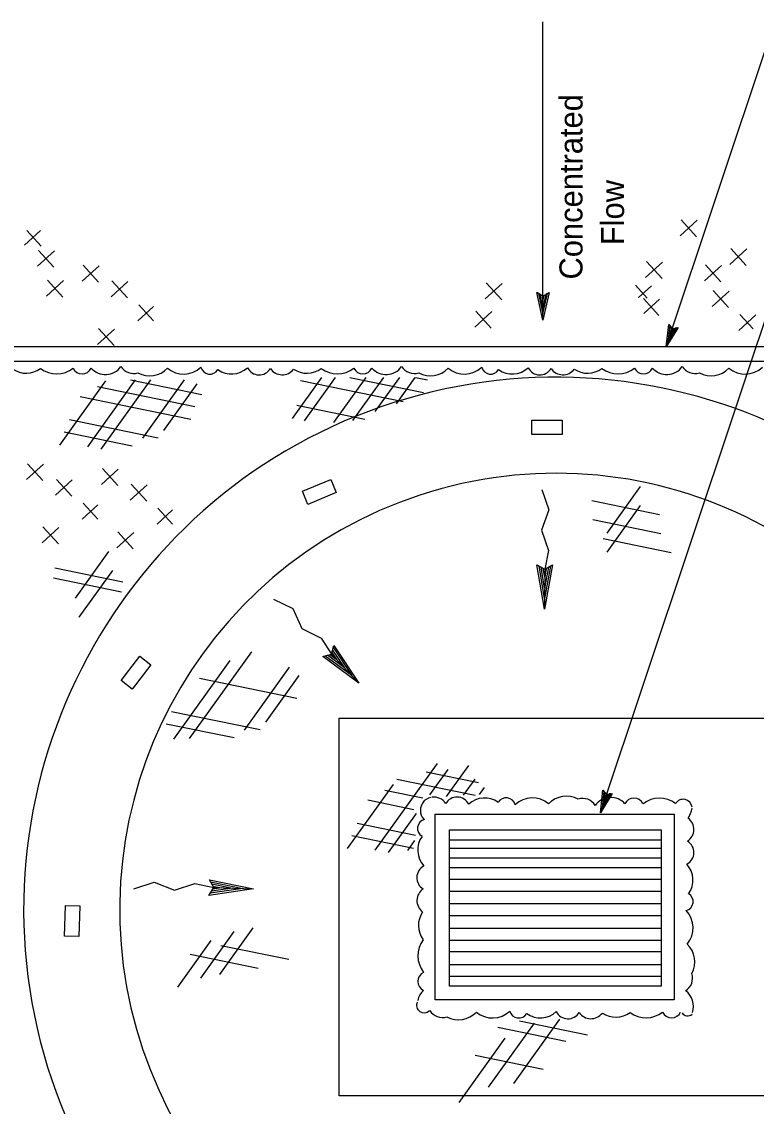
# Model space of a CAD drawing. Extents: x 6708945 to 6710368, y 1871409 to 1872338.
# Drawn here: x 6709044.1 to 6709235.1, y 1871623 to 1871904.9 of the extents above; entities that cross this region are included whole.
import ezdxf

# ---------------------------------------------------------------- set-up
doc = ezdxf.new("R2010")
doc.units = 0
for name, color, linetype in [('1 Control', 7, 'Continuous'), ('57 Undefined', 7, 'Continuous'), ('60 Nongeo Data', 7, 'Continuous'), ('62 As-Built Chng', 7, 'Continuous'), ('63 Undefined', 7, 'Continuous')]:
    doc.layers.add(name, color=color, linetype=linetype)

msp = doc.modelspace()

# ---------------------------------------------------------------- linework, layer by layer
at = {"layer": '1 Control'}
for p, q in [((6709178.02, 1871834.47), (6709178.02, 1871834.47)), ((6709181.22, 1871834.47), (6709181.22, 1871834.47)), ((6709179.61, 1871827.27), (6709179.61, 1871827.27))]:
    msp.add_line(p, q, dxfattribs=at)
msp.add_lwpolyline([(6709181.22, 1871834.47), (6709179.61, 1871827.27), (6709178.01, 1871834.47), (6709178.44, 1871834.21), (6709179.61, 1871828.93), (6709180.79, 1871834.21), (6709180.37, 1871833.96), (6709179.61, 1871830.58), (6709178.87, 1871833.95), (6709179.29, 1871833.7), (6709179.62, 1871832.24), (6709179.94, 1871833.7), (6709179.61, 1871833.51), (6709178.01, 1871834.47), (6709179.61, 1871833.51)], close=True, dxfattribs=at)
at = {"layer": '57 Undefined'}
for p, q in [((6709179.61, 1871827.27), (6709179.61, 1871904.86)), ((6709211.7, 1871820.34), (6709238.21, 1871899.71)), ((6709194.57, 1871699.25), (6709249.1, 1871862.48))]:
    msp.add_line(p, q, dxfattribs=at)
at = {"layer": '60 Nongeo Data'}
for p, q in [((6709212.31, 1871826.2), (6709212.31, 1871826.2)), ((6709214.74, 1871825.39), (6709214.74, 1871825.39)), ((6709211.7, 1871820.34), (6709211.7, 1871820.34)), ((6709195.18, 1871705.12), (6709195.18, 1871705.12)), ((6709197.62, 1871704.31), (6709197.62, 1871704.31)), ((6709194.57, 1871699.25), (6709194.57, 1871699.25))]:
    msp.add_line(p, q, dxfattribs=at)
for points in [[(6709214.74, 1871825.39), (6709211.7, 1871820.34), (6709212.31, 1871826.2), (6709212.57, 1871825.9), (6709212.11, 1871821.6), (6709214.35, 1871825.31), (6709213.97, 1871825.22), (6709212.54, 1871822.85), (6709212.82, 1871825.6), (6709213.08, 1871825.3), (6709212.96, 1871824.11), (6709213.58, 1871825.14), (6709213.28, 1871825.07), (6709212.31, 1871826.2), (6709213.28, 1871825.07)], [(6709197.62, 1871704.31), (6709194.57, 1871699.25), (6709195.18, 1871705.12), (6709195.44, 1871704.82), (6709194.99, 1871700.52), (6709197.23, 1871704.22), (6709196.84, 1871704.14), (6709195.41, 1871701.77), (6709195.7, 1871704.52), (6709195.96, 1871704.21), (6709195.83, 1871703.03), (6709196.45, 1871704.05), (6709196.15, 1871703.99), (6709195.18, 1871705.12), (6709196.15, 1871703.99)]]:
    msp.add_lwpolyline(points, close=True, dxfattribs=at)
msp.add_arc((6709182.99, 1871674.08), 113.4, 20.4401, 11.3417, dxfattribs=at)
at = {"layer": '62 As-Built Chng'}
for p, q in [((6709215.29, 1871849.23), (6709219.68, 1871853.25)), ((6709215.54, 1871853.38), (6709219.56, 1871848.98)), ((6709044.85, 1871846.79), (6709049, 1871850.59)), ((6709045.39, 1871850.63), (6709049.12, 1871846.54)), ((6709048.45, 1871845.42), (6709052.47, 1871841.02)), ((6709228.2, 1871841.77), (6709232.6, 1871845.79)), ((6709228.45, 1871845.91), (6709232.47, 1871841.52)), ((6709048.2, 1871841.28), (6709052.6, 1871845.29)), ((6709059.8, 1871837.41), (6709064.2, 1871841.42)), ((6709060.05, 1871841.55), (6709064.07, 1871837.15)), ((6709206.32, 1871838.35), (6709210.72, 1871842.37)), ((6709206.57, 1871842.5), (6709210.59, 1871838.1)), ((6709221.62, 1871837.51), (6709226.02, 1871841.53)), ((6709221.87, 1871841.66), (6709225.89, 1871837.26)), ((6709050.52, 1871833.54), (6709054.92, 1871837.56)), ((6709050.77, 1871837.68), (6709054.79, 1871833.28)), ((6709067.31, 1871833.34), (6709071.71, 1871837.36)), ((6709067.56, 1871837.49), (6709071.58, 1871833.09)), ((6709164.87, 1871836.99), (6709168.89, 1871832.59)), ((6709164.62, 1871832.84), (6709169.02, 1871836.86)), ((6709203.7, 1871836.37), (6709206.74, 1871833.04)), ((6709204.48, 1871833.16), (6709207.85, 1871836.24)), ((6709223.62, 1871830.83), (6709228.01, 1871834.85)), ((6709223.87, 1871834.98), (6709227.88, 1871830.58)), ((6709074.52, 1871831.3), (6709078.32, 1871827.14)), ((6709205.76, 1871832.89), (6709209.78, 1871828.49)), ((6709205.83, 1871829.03), (6709209.91, 1871832.76)), ((6709074.27, 1871827.15), (6709078.33, 1871830.86)), ((6709161.91, 1871825.49), (6709166.31, 1871829.51)), ((6709162.16, 1871829.63), (6709166.18, 1871825.24)), ((6709230.53, 1871824.6), (6709234.97, 1871828.66)), ((6709230.83, 1871828.79), (6709234.29, 1871825)), ((6709063.83, 1871820.96), (6709068.23, 1871824.98)), ((6709064.08, 1871825.11), (6709068.1, 1871820.71)), ((6709045.34, 1871785.84), (6709049.74, 1871789.86)), ((6709045.59, 1871789.98), (6709049.61, 1871785.59)), ((6709064.81, 1871784.55), (6709069.21, 1871788.57)), ((6709065.07, 1871788.7), (6709069.08, 1871784.3)), ((6709052.85, 1871781.78), (6709057.25, 1871785.8)), ((6709053.1, 1871785.92), (6709057.12, 1871781.52)), ((6709072.32, 1871780.49), (6709076.72, 1871784.51)), ((6709072.57, 1871784.63), (6709076.59, 1871780.23)), ((6709059.81, 1871775.59), (6709063.87, 1871779.29)), ((6709060.06, 1871779.73), (6709063.86, 1871775.58)), ((6709079.28, 1871774.3), (6709083.34, 1871778)), ((6709079.53, 1871778.44), (6709083.33, 1871774.29)), ((6709049.37, 1871769.39), (6709053.77, 1871773.41)), ((6709049.62, 1871773.54), (6709053.64, 1871769.14)), ((6709068.84, 1871768.11), (6709073.24, 1871772.12)), ((6709069.09, 1871772.25), (6709073.11, 1871767.85)), ((6709152.08, 1871712.08), (6709135.91, 1871689.53)), ((6709154.89, 1871710.49), (6709150.16, 1871703.9)), ((6709160.23, 1871711.54), (6709154.44, 1871703.45)), ((6709141.67, 1871707.98), (6709162.03, 1871703.8)), ((6709149.23, 1871709.9), (6709162.85, 1871707.11)), ((6709161.9, 1871708.03), (6709158.9, 1871703.84)), ((6709140.66, 1871706.62), (6709128.7, 1871689.94)), ((6709138.55, 1871705.16), (6709148.38, 1871703.14)), ((6709164.37, 1871705.85), (6709163.02, 1871703.97)), ((6709134.05, 1871702.58), (6709146.05, 1871700.11)), ((6709146.67, 1871699.03), (6709139.41, 1871688.91)), ((6709131.3, 1871696.57), (6709146.47, 1871693.46)), ((6709129.92, 1871693.35), (6709145.96, 1871690.06)), ((6709146.24, 1871692.02), (6709144.37, 1871689.41)), ((6709155.41, 1871692.22), (6709210.3, 1871692.22)), ((6709155.41, 1871690.09), (6709210.3, 1871690.09)), ((6709155.41, 1871687.55), (6709210.3, 1871687.55)), ((6709155.41, 1871685), (6709210.3, 1871685)), ((6709155.41, 1871682.02), (6709210.3, 1871682.02)), ((6709155.41, 1871678.91), (6709210.3, 1871678.91)), ((6709155.41, 1871675.65), (6709210.3, 1871675.65)), ((6709155.41, 1871672.54), (6709210.3, 1871672.54)), ((6709155.41, 1871669.28), (6709210.3, 1871669.28)), ((6709155.41, 1871666.17), (6709210.3, 1871666.17)), ((6709155.41, 1871663.19), (6709210.3, 1871663.19)), ((6709155.41, 1871659.8), (6709210.3, 1871659.8)), ((6709155.41, 1871656.82), (6709210.3, 1871656.82)), ((6709183.96, 1871645.6), (6709171.99, 1871628.91)), ((6709177.35, 1871644.61), (6709165.38, 1871627.92)), ((6709167.93, 1871643.54), (6709185.59, 1871639.92)), ((6709173.54, 1871645.19), (6709191.21, 1871641.57)), ((6709169.75, 1871640.65), (6709157.78, 1871623.97)), ((6709161.98, 1871636.29), (6709179.64, 1871632.66))]:
    msp.add_line(p, q, dxfattribs=at)
for points in [[(6709036.13, 1871820.42), (6709330.46, 1871820.42), (6709330.46, 1871528.03), (6709036.13, 1871528.03)], [(6709040.24, 1871816.63), (6709326.68, 1871816.63), (6709326.68, 1871531.81), (6709040.24, 1871531.81)], [(6709176.7, 1871797.57), (6709176.7, 1871801.26), (6709184.64, 1871801.26), (6709184.64, 1871797.57)], [(6709118.52, 1871779.4), (6709117.1, 1871782.81), (6709124.43, 1871785.88), (6709125.85, 1871782.47)], [(6709072.84, 1871731.42), (6709069.92, 1871733.67), (6709074.77, 1871739.97), (6709077.69, 1871737.71)], [(6709126.63, 1871723.85), (6709238.71, 1871723.85), (6709238.71, 1871625.65), (6709126.63, 1871625.65)], [(6709151.59, 1871698.89), (6709213.75, 1871698.89), (6709213.75, 1871650.61), (6709151.59, 1871650.61)], [(6709155.34, 1871694.83), (6709210.37, 1871694.83), (6709210.37, 1871654.22), (6709155.34, 1871654.22)], [(6709058.94, 1871667.1), (6709055.25, 1871667.22), (6709055.51, 1871675.16), (6709059.2, 1871675.04)]]:
    msp.add_lwpolyline(points, close=True, dxfattribs=at)
for centre, radius, start, end in [((6709182.99, 1871674.08), 138.36, 19.738, 11.782), ((6709151.01, 1871699.82), 3.27, 137.0454, 222.9546), ((6709151.28, 1871699.64), 3.68, 101.8237, 143.3403), ((6709151.28, 1871699.64), 3.68, 33.6905, 97.7757), ((6709157.27, 1871699.93), 3.41, 27.0211, 149.1913), ((6709164.46, 1871697), 6.1, 54.5002, 132.8354), ((6709170.06, 1871700.75), 2.4, 14.0578, 149.3233), ((6709176.88, 1871696.58), 6.54, 49.9986, 133.3536), ((6709185.72, 1871697.23), 6.36, 61.3634, 136.8458), ((6709189.93, 1871699.11), 3.88, 32.3474, 107.3796), ((6709197.24, 1871698.23), 5, 42.1292, 143.705), ((6709203.29, 1871700.52), 2.57, 24.5196, 155.4804), ((6709209.94, 1871696.06), 7, 53.3979, 127.9353), ((6709216.08, 1871700.43), 2.33, 7.9172, 147.5353), ((6709212.25, 1871701.38), 6.2, 325.656, 351.2205), ((6709149.41, 1871695.2), 2.4, 104.0578, 239.3233), ((6709215.18, 1871694.94), 3.68, 303.6905, 53.3403), ((6709153.16, 1871689.59), 6.1, 144.5002, 222.8354), ((6709215.47, 1871688.95), 3.41, 297.0211, 59.1913), ((6709150.23, 1871682.4), 3.41, 117.0211, 239.1913), ((6709212.54, 1871681.76), 6.1, 324.5002, 42.8354), ((6709150.53, 1871676.42), 3.68, 123.6905, 233.3403), ((6709216.29, 1871676.16), 2.4, 284.0578, 59.3233), ((6709153.45, 1871669.97), 6.2, 145.656, 216.6973), ((6709212.12, 1871669.34), 6.54, 319.9986, 43.3536), ((6709154.1, 1871662.09), 7, 143.3979, 217.9353), ((6709212.77, 1871660.5), 6.36, 331.3634, 46.8458), ((6709149.65, 1871655.44), 2.57, 114.5196, 245.4804), ((6709214.65, 1871656.29), 3.88, 302.3474, 17.3796), ((6709151.93, 1871649.39), 5, 132.1292, 167.3432), ((6709213.77, 1871648.98), 5, 341.0585, 53.705), ((6709148.72, 1871649.21), 1.96, 154.4139, 315.1102), ((6709153.46, 1871649.93), 3.88, 212.3474, 287.3796), ((6709157.67, 1871651.81), 6.36, 241.3634, 316.8458), ((6709166.52, 1871652.47), 6.54, 229.9986, 313.3536), ((6709173.33, 1871648.3), 2.4, 194.0578, 329.3233), ((6709178.94, 1871652.04), 6.1, 234.5002, 312.8354), ((6709186.12, 1871649.12), 3.41, 207.0211, 329.1913), ((6709192.11, 1871649.41), 3.68, 213.6905, 323.3403), ((6709198.56, 1871652.33), 6.2, 235.656, 306.6973), ((6709206.44, 1871652.98), 7, 233.3979, 307.9353), ((6709213.08, 1871648.53), 2.57, 204.5196, 335.4804), ((6709217.24, 1871648.13), 1.68, 210.6418, 313.085)]:
    msp.add_arc(centre, radius, start, end, dxfattribs=at)
at = {"layer": '63 Undefined'}
for p, q in [((6709073.6, 1871811.75), (6709061.17, 1871794.41)), ((6709077.55, 1871811.75), (6709064.67, 1871793.79)), ((6709072.37, 1871811.75), (6709090.95, 1871807.93)), ((6709086.32, 1871811.75), (6709075.46, 1871796.6)), ((6709122.08, 1871812.41), (6709114.44, 1871801.75)), ((6709116.54, 1871811.62), (6709143.31, 1871806.13)), ((6709125.62, 1871812.41), (6709117.53, 1871801.13)), ((6709133.54, 1871812.41), (6709125.16, 1871800.72)), ((6709129.44, 1871812.41), (6709148.55, 1871808.48)), ((6709138.13, 1871812.41), (6709130.11, 1871801.22)), ((6709142.31, 1871812.41), (6709135.95, 1871803.52)), ((6709146.35, 1871812.41), (6709141.43, 1871805.55)), ((6709146.51, 1871812.41), (6709149.58, 1871811.77)), ((6709065.92, 1871811.51), (6709053.95, 1871794.82)), ((6709063.81, 1871810.04), (6709089.1, 1871804.85)), ((6709089.63, 1871810.73), (6709080.95, 1871798.62)), ((6709059.31, 1871807.46), (6709088.07, 1871801.56)), ((6709115.66, 1871805.16), (6709133.32, 1871801.54)), ((6709056.56, 1871801.45), (6709079.57, 1871796.73)), ((6709055.17, 1871798.24), (6709072.84, 1871794.61)), ((6709204.93, 1871784.02), (6709196.25, 1871771.91)), ((6709192.29, 1871780.43), (6709209.95, 1871776.81)), ((6709204.93, 1871779.08), (6709196.25, 1871766.96)), ((6709192.62, 1871775.48), (6709210.28, 1871771.86)), ((6709195.26, 1871770.54), (6709212.93, 1871766.91)), ((6709066.67, 1871767.19), (6709057.98, 1871755.07)), ((6709180, 1871752.17), (6709178.07, 1871763.73)), ((6709178.07, 1871763.73), (6709180.1, 1871762.53)), ((6709182.14, 1871763.69), (6709180, 1871752.17)), ((6709180.1, 1871762.53), (6709182.14, 1871763.69)), ((6709052.7, 1871762.93), (6709070.36, 1871759.31)), ((6709067.66, 1871762.24), (6709058.97, 1871750.12)), ((6709180.03, 1871754.93), (6709178.6, 1871763.41)), ((6709180.05, 1871757.67), (6709179.15, 1871763.09)), ((6709180.08, 1871760.47), (6709179.69, 1871762.76)), ((6709181.6, 1871763.38), (6709180.03, 1871754.93)), ((6709181.05, 1871763.07), (6709180.05, 1871757.67)), ((6709180.5, 1871762.76), (6709180.08, 1871760.47)), ((6709052.37, 1871760.29), (6709070.03, 1871756.67)), ((6709103.84, 1871741.13), (6709087.67, 1871718.58)), ((6709124.64, 1871740.46), (6709125.29, 1871742.72)), ((6709124.94, 1871741.51), (6709127.99, 1871736.94)), ((6709125.12, 1871742.12), (6709129.89, 1871734.97)), ((6709125.29, 1871742.72), (6709131.79, 1871732.97)), ((6709098.21, 1871738.83), (6709083.55, 1871718.37)), ((6709122.35, 1871739.91), (6709124.64, 1871740.46)), ((6709131.79, 1871732.97), (6709122.35, 1871739.91)), ((6709129.89, 1871734.97), (6709122.95, 1871740.05)), ((6709127.99, 1871736.94), (6709123.57, 1871740.2)), ((6709126.06, 1871738.97), (6709124.18, 1871740.35)), ((6709124.77, 1871740.9), (6709126.06, 1871738.97)), ((6709113.66, 1871737.08), (6709101.96, 1871720.76)), ((6709090.31, 1871734.21), (6709115.6, 1871729.01)), ((6709116.13, 1871734.9), (6709107.45, 1871722.79)), ((6709083.06, 1871725.62), (6709106.07, 1871720.9)), ((6709081.67, 1871722.4), (6709099.34, 1871718.78)), ((6709092.77, 1871677.8), (6709094.01, 1871679.8)), ((6709104.36, 1871679.5), (6709092.77, 1871677.8)), ((6709092.89, 1871681.87), (6709104.36, 1871679.5)), ((6709094.01, 1871679.8), (6709092.89, 1871681.87)), ((6709101.61, 1871679.58), (6709093.11, 1871678.33)), ((6709093.19, 1871681.32), (6709101.61, 1871679.58)), ((6709098.87, 1871679.66), (6709093.44, 1871678.86)), ((6709093.49, 1871680.77), (6709098.87, 1871679.66)), ((6709096.07, 1871679.74), (6709093.77, 1871679.4)), ((6709093.79, 1871680.21), (6709096.07, 1871679.74)), ((6709099.24, 1871668.39), (6709090.55, 1871656.27)), ((6709104.19, 1871669.38), (6709095.51, 1871657.26)), ((6709093.29, 1871666.08), (6709084.6, 1871653.96)), ((6709087.91, 1871662.49), (6709105.58, 1871658.86)), ((6709095.85, 1871664.8), (6709113.51, 1871661.17))]:
    msp.add_line(p, q, dxfattribs=at)
for points in [[(6709179.33, 1871783.31), (6709181.19, 1871778.01), (6709179.24, 1871772.74), (6709181.09, 1871767.44), (6709180.1, 1871762.53), (6709180, 1871752.17)], [(6709109.59, 1871754.81), (6709114.62, 1871752.31), (6709116.9, 1871747.18), (6709121.92, 1871744.67), (6709124.64, 1871740.46), (6709131.79, 1871732.97)], [(6709073.22, 1871679.45), (6709078.56, 1871681.2), (6709083.79, 1871679.14), (6709089.12, 1871680.89), (6709094.01, 1871679.8), (6709104.36, 1871679.5)]]:
    msp.add_lwpolyline(points, dxfattribs=at)
for centre, radius, start, end in [((6709045.28, 1871819.69), 6.2, 235.656, 306.6973), ((6709053.16, 1871820.34), 7, 233.3979, 307.9353), ((6709059.8, 1871815.88), 2.57, 204.5196, 335.4804), ((6709065.86, 1871818.17), 5, 222.1292, 323.705), ((6709073.17, 1871817.29), 3.88, 212.3474, 287.3796), ((6709077.37, 1871819.17), 6.36, 241.3634, 316.8458), ((6709086.22, 1871819.83), 6.54, 229.9986, 313.3536), ((6709093.03, 1871815.65), 2.4, 194.0578, 329.3233), ((6709098.64, 1871819.4), 6.1, 234.5002, 312.8354), ((6709105.83, 1871816.47), 3.41, 207.0211, 329.1913), ((6709111.82, 1871816.77), 3.68, 213.6905, 323.3403), ((6709118.26, 1871819.69), 6.2, 235.656, 306.6973), ((6709126.14, 1871820.34), 7, 233.3979, 307.9353), ((6709132.79, 1871815.88), 2.57, 204.5196, 335.4804), ((6709138.84, 1871818.17), 5, 222.1292, 323.705), ((6709146.15, 1871817.29), 3.88, 212.3474, 287.3796), ((6709150.36, 1871819.17), 6.36, 241.3634, 316.8458), ((6709159.2, 1871819.83), 6.54, 229.9986, 313.3536), ((6709166.02, 1871815.65), 2.4, 194.0578, 329.3233), ((6709171.62, 1871819.4), 6.1, 234.5002, 312.8354), ((6709178.81, 1871816.47), 3.41, 207.0211, 329.1913), ((6709184.8, 1871816.77), 3.68, 213.6905, 323.3403), ((6709191.24, 1871819.69), 6.2, 235.656, 306.6973), ((6709199.12, 1871820.34), 7, 233.3979, 307.9353), ((6709205.77, 1871815.88), 2.57, 204.5196, 335.4804), ((6709211.82, 1871818.17), 5, 222.1292, 323.705), ((6709219.13, 1871817.29), 3.88, 212.3474, 287.3796), ((6709223.34, 1871819.17), 6.36, 241.3634, 316.8458), ((6709232.19, 1871819.83), 6.54, 229.9986, 313.3536)]:
    msp.add_arc(centre, radius, start, end, dxfattribs=at)

# ---------------------------------------------------------------- texts
at = {"layer": '57 Undefined'}
for s, p in [('Concentrated', (6709189.91, 1871837.86)), ('    Flow', (6709200.71, 1871837.86))]:
    msp.add_text(s, height=6, rotation=90, dxfattribs=at).set_placement(p)

doc.saveas('drawing.dxf')
